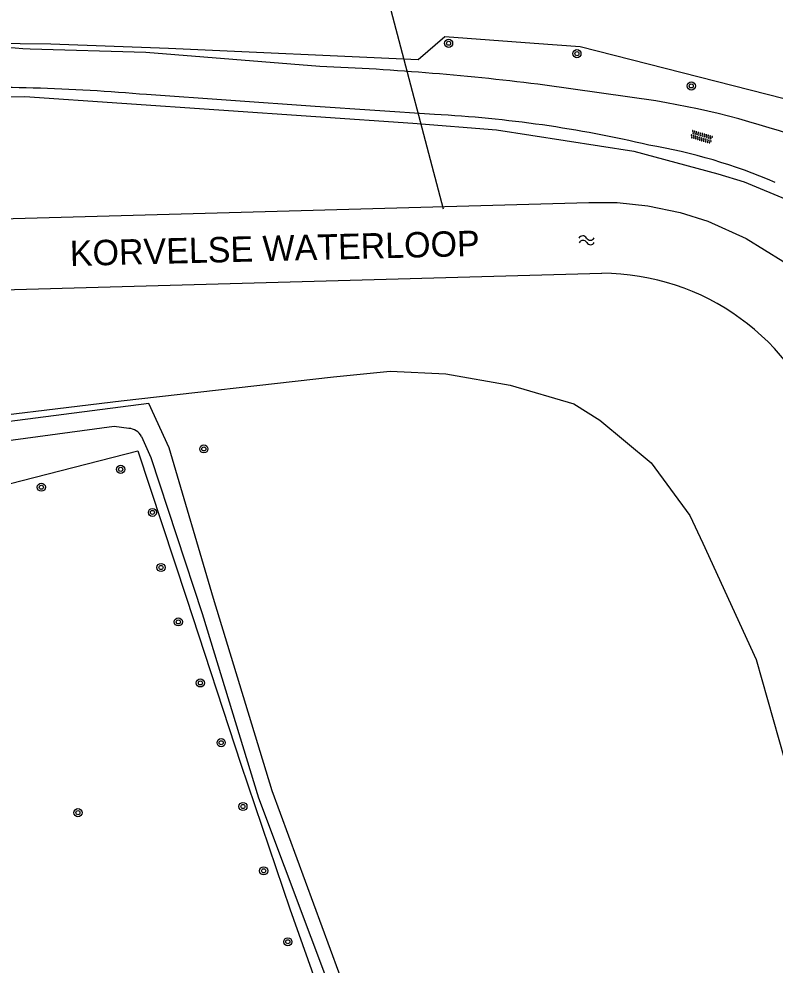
# Model space of a CAD drawing. Extents: x 135999 to 138000, y 396000 to 398501.
# Drawn here: x 136593.9 to 136668.2, y 396615.1 to 396708.2 of the extents above; entities that cross this region are included whole.
import ezdxf

# ---------------------------------------------------------------- set-up
doc = ezdxf.new("R2010")
doc.units = 0
for name, color, linetype in [('gg-afsc-faunaraster', 7, 'Continuous'), ('gg-afsc-lijn faunaraster', 7, 'Continuous'), ('gg-anno-naam water', 7, 'Continuous'), ('gg-knt-onverhard', 7, 'Continuous'), ('gg-kntw-beschoeiing', 7, 'Continuous'), ('gg-kwrk-duiker nz buis', 7, 'Continuous'), ('gt-symb-boom', 7, 'Continuous'), ('gt-symb-overige verharding', 7, 'Continuous'), ('gt-symb-watersymbool', 7, 'Continuous')]:
    doc.layers.add(name, color=color, linetype=linetype)

# ---------------------------------------------------------------- blocks, each defined once
blk = doc.blocks.new('gt0-OVH')
at = {"layer": 'gt-symb-overige verharding'}
for points in [[(-0.972, 0.298), (-0.967, 0.308), (-0.965, 0.319), (-0.966, 0.33), (-0.971, 0.34), (-0.978, 0.348), (-0.988, 0.353), (-0.999, 0.355), (-1.01, 0.354), (-1.02, 0.349), (-1.028, 0.342), (-1.033, 0.332), (-1.035, 0.321), (-1.034, 0.31), (-1.029, 0.3), (-1.022, 0.292), (-1.012, 0.287), (-1.001, 0.285), (-0.99, 0.286), (-0.98, 0.291)], [(-0.872, 0.106), (-0.867, 0.116), (-0.865, 0.126), (-0.866, 0.137), (-0.871, 0.147), (-0.878, 0.156), (-0.888, 0.161), (-0.899, 0.163), (-0.91, 0.162), (-0.92, 0.157), (-0.928, 0.15), (-0.933, 0.14), (-0.935, 0.129), (-0.934, 0.118), (-0.929, 0.108), (-0.922, 0.1), (-0.912, 0.095), (-0.901, 0.092), (-0.89, 0.094), (-0.88, 0.098)], [(-0.772, 0.298), (-0.767, 0.308), (-0.765, 0.319), (-0.766, 0.33), (-0.771, 0.34), (-0.778, 0.348), (-0.788, 0.353), (-0.799, 0.355), (-0.81, 0.354), (-0.82, 0.349), (-0.828, 0.342), (-0.833, 0.332), (-0.835, 0.321), (-0.834, 0.31), (-0.829, 0.3), (-0.822, 0.292), (-0.812, 0.287), (-0.801, 0.285), (-0.79, 0.286), (-0.78, 0.291)], [(-0.672, 0.106), (-0.667, 0.116), (-0.665, 0.126), (-0.666, 0.137), (-0.671, 0.147), (-0.678, 0.156), (-0.688, 0.161), (-0.699, 0.163), (-0.71, 0.162), (-0.72, 0.157), (-0.728, 0.15), (-0.733, 0.14), (-0.735, 0.129), (-0.734, 0.118), (-0.729, 0.108), (-0.722, 0.1), (-0.712, 0.095), (-0.701, 0.092), (-0.69, 0.094), (-0.68, 0.098)], [(-0.572, 0.298), (-0.567, 0.308), (-0.565, 0.319), (-0.566, 0.33), (-0.571, 0.34), (-0.578, 0.348), (-0.588, 0.353), (-0.599, 0.355), (-0.61, 0.354), (-0.62, 0.349), (-0.628, 0.342), (-0.633, 0.332), (-0.635, 0.321), (-0.634, 0.31), (-0.629, 0.3), (-0.622, 0.292), (-0.612, 0.287), (-0.601, 0.285), (-0.59, 0.286), (-0.58, 0.291)], [(-0.472, 0.106), (-0.467, 0.116), (-0.465, 0.126), (-0.466, 0.137), (-0.471, 0.147), (-0.478, 0.156), (-0.488, 0.161), (-0.499, 0.163), (-0.51, 0.162), (-0.52, 0.157), (-0.528, 0.15), (-0.533, 0.14), (-0.535, 0.129), (-0.534, 0.118), (-0.529, 0.108), (-0.522, 0.1), (-0.512, 0.095), (-0.501, 0.092), (-0.49, 0.094), (-0.48, 0.098)], [(-0.372, 0.298), (-0.367, 0.308), (-0.365, 0.319), (-0.366, 0.33), (-0.371, 0.34), (-0.378, 0.348), (-0.388, 0.353), (-0.399, 0.355), (-0.41, 0.354), (-0.42, 0.349), (-0.428, 0.342), (-0.433, 0.332), (-0.435, 0.321), (-0.434, 0.31), (-0.429, 0.3), (-0.422, 0.292), (-0.412, 0.287), (-0.401, 0.285), (-0.39, 0.286), (-0.38, 0.291)], [(-0.272, 0.106), (-0.267, 0.116), (-0.265, 0.126), (-0.266, 0.137), (-0.271, 0.147), (-0.278, 0.156), (-0.288, 0.161), (-0.299, 0.163), (-0.31, 0.162), (-0.32, 0.157), (-0.328, 0.15), (-0.333, 0.14), (-0.335, 0.129), (-0.334, 0.118), (-0.329, 0.108), (-0.322, 0.1), (-0.312, 0.095), (-0.301, 0.092), (-0.29, 0.094), (-0.28, 0.098)], [(-0.172, 0.298), (-0.167, 0.308), (-0.165, 0.319), (-0.166, 0.33), (-0.171, 0.34), (-0.178, 0.348), (-0.188, 0.353), (-0.199, 0.355), (-0.21, 0.354), (-0.22, 0.349), (-0.228, 0.342), (-0.233, 0.332), (-0.235, 0.321), (-0.234, 0.31), (-0.229, 0.3), (-0.222, 0.292), (-0.212, 0.287), (-0.201, 0.285), (-0.19, 0.286), (-0.18, 0.291)], [(-0.072, 0.106), (-0.067, 0.116), (-0.065, 0.126), (-0.066, 0.137), (-0.071, 0.147), (-0.078, 0.156), (-0.088, 0.161), (-0.099, 0.163), (-0.11, 0.162), (-0.12, 0.157), (-0.128, 0.15), (-0.133, 0.14), (-0.135, 0.129), (-0.134, 0.118), (-0.129, 0.108), (-0.122, 0.1), (-0.112, 0.095), (-0.101, 0.092), (-0.09, 0.094), (-0.08, 0.098)], [(0.028, 0.298), (0.033, 0.308), (0.035, 0.319), (0.034, 0.33), (0.029, 0.34), (0.022, 0.348), (0.012, 0.353), (0.001, 0.355), (-0.01, 0.354), (-0.02, 0.349), (-0.028, 0.342), (-0.033, 0.332), (-0.035, 0.321), (-0.034, 0.31), (-0.029, 0.3), (-0.022, 0.292), (-0.012, 0.287), (-0.001, 0.285), (0.01, 0.286), (0.02, 0.291)], [(0.128, 0.106), (0.133, 0.116), (0.135, 0.126), (0.134, 0.137), (0.129, 0.147), (0.122, 0.156), (0.112, 0.161), (0.101, 0.163), (0.09, 0.162), (0.08, 0.157), (0.072, 0.15), (0.067, 0.14), (0.065, 0.129), (0.066, 0.118), (0.071, 0.108), (0.078, 0.1), (0.088, 0.095), (0.099, 0.092), (0.11, 0.094), (0.12, 0.098)], [(0.228, 0.298), (0.233, 0.308), (0.235, 0.319), (0.234, 0.33), (0.229, 0.34), (0.222, 0.348), (0.212, 0.353), (0.201, 0.355), (0.19, 0.354), (0.18, 0.349), (0.172, 0.342), (0.167, 0.332), (0.165, 0.321), (0.166, 0.31), (0.171, 0.3), (0.178, 0.292), (0.188, 0.287), (0.199, 0.285), (0.21, 0.286), (0.22, 0.291)], [(0.328, 0.106), (0.333, 0.116), (0.335, 0.126), (0.334, 0.137), (0.329, 0.147), (0.322, 0.156), (0.312, 0.161), (0.301, 0.163), (0.29, 0.162), (0.28, 0.157), (0.272, 0.15), (0.267, 0.14), (0.265, 0.129), (0.266, 0.118), (0.271, 0.108), (0.278, 0.1), (0.288, 0.095), (0.299, 0.092), (0.31, 0.094), (0.32, 0.098)], [(0.428, 0.298), (0.433, 0.308), (0.435, 0.319), (0.434, 0.33), (0.429, 0.34), (0.422, 0.348), (0.412, 0.353), (0.401, 0.355), (0.39, 0.354), (0.38, 0.349), (0.372, 0.342), (0.367, 0.332), (0.365, 0.321), (0.366, 0.31), (0.371, 0.3), (0.378, 0.292), (0.388, 0.287), (0.399, 0.285), (0.41, 0.286), (0.42, 0.291)], [(0.528, 0.106), (0.533, 0.116), (0.535, 0.126), (0.534, 0.137), (0.529, 0.147), (0.522, 0.156), (0.512, 0.161), (0.501, 0.163), (0.49, 0.162), (0.48, 0.157), (0.472, 0.15), (0.467, 0.14), (0.465, 0.129), (0.466, 0.118), (0.471, 0.108), (0.478, 0.1), (0.488, 0.095), (0.499, 0.092), (0.51, 0.094), (0.52, 0.098)], [(0.628, 0.298), (0.633, 0.308), (0.635, 0.319), (0.634, 0.33), (0.629, 0.34), (0.622, 0.348), (0.612, 0.353), (0.601, 0.355), (0.59, 0.354), (0.58, 0.349), (0.572, 0.342), (0.567, 0.332), (0.565, 0.321), (0.566, 0.31), (0.571, 0.3), (0.578, 0.292), (0.588, 0.287), (0.599, 0.285), (0.61, 0.286), (0.62, 0.291)], [(0.728, 0.106), (0.733, 0.116), (0.735, 0.126), (0.734, 0.137), (0.729, 0.147), (0.722, 0.156), (0.712, 0.161), (0.701, 0.163), (0.69, 0.162), (0.68, 0.157), (0.672, 0.15), (0.667, 0.14), (0.665, 0.129), (0.666, 0.118), (0.671, 0.108), (0.678, 0.1), (0.688, 0.095), (0.699, 0.092), (0.71, 0.094), (0.72, 0.098)], [(0.828, 0.298), (0.833, 0.308), (0.835, 0.319), (0.834, 0.33), (0.829, 0.34), (0.822, 0.348), (0.812, 0.353), (0.801, 0.355), (0.79, 0.354), (0.78, 0.349), (0.772, 0.342), (0.767, 0.332), (0.765, 0.321), (0.766, 0.31), (0.771, 0.3), (0.778, 0.292), (0.788, 0.287), (0.799, 0.285), (0.81, 0.286), (0.82, 0.291)], [(0.928, 0.106), (0.933, 0.116), (0.935, 0.126), (0.934, 0.137), (0.929, 0.147), (0.922, 0.156), (0.912, 0.161), (0.901, 0.163), (0.89, 0.162), (0.88, 0.157), (0.872, 0.15), (0.867, 0.14), (0.865, 0.129), (0.866, 0.118), (0.871, 0.108), (0.878, 0.1), (0.888, 0.095), (0.899, 0.092), (0.91, 0.094), (0.92, 0.098)], [(1.028, 0.298), (1.033, 0.308), (1.035, 0.319), (1.034, 0.33), (1.029, 0.34), (1.022, 0.348), (1.012, 0.353), (1.001, 0.355), (0.99, 0.354), (0.98, 0.349), (0.972, 0.342), (0.967, 0.332), (0.965, 0.321), (0.966, 0.31), (0.971, 0.3), (0.978, 0.292), (0.988, 0.287), (0.999, 0.285), (1.01, 0.286), (1.02, 0.291)], [(-0.972, -0.142), (-0.967, -0.132), (-0.965, -0.121), (-0.966, -0.11), (-0.971, -0.1), (-0.978, -0.092), (-0.988, -0.087), (-0.999, -0.085), (-1.01, -0.086), (-1.02, -0.091), (-1.028, -0.098), (-1.033, -0.108), (-1.035, -0.119), (-1.034, -0.13), (-1.029, -0.14), (-1.022, -0.148), (-1.012, -0.153), (-1.001, -0.155), (-0.99, -0.154), (-0.98, -0.149)], [(-0.872, -0.334), (-0.867, -0.324), (-0.865, -0.314), (-0.866, -0.303), (-0.871, -0.293), (-0.878, -0.284), (-0.888, -0.279), (-0.899, -0.277), (-0.91, -0.278), (-0.92, -0.283), (-0.928, -0.29), (-0.933, -0.3), (-0.935, -0.311), (-0.934, -0.322), (-0.929, -0.332), (-0.922, -0.34), (-0.912, -0.345), (-0.901, -0.348), (-0.89, -0.346), (-0.88, -0.342)], [(-0.772, -0.142), (-0.767, -0.132), (-0.765, -0.121), (-0.766, -0.11), (-0.771, -0.1), (-0.778, -0.092), (-0.788, -0.087), (-0.799, -0.085), (-0.81, -0.086), (-0.82, -0.091), (-0.828, -0.098), (-0.833, -0.108), (-0.835, -0.119), (-0.834, -0.13), (-0.829, -0.14), (-0.822, -0.148), (-0.812, -0.153), (-0.801, -0.155), (-0.79, -0.154), (-0.78, -0.149)], [(-0.672, -0.334), (-0.667, -0.324), (-0.665, -0.314), (-0.666, -0.303), (-0.671, -0.293), (-0.678, -0.284), (-0.688, -0.279), (-0.699, -0.277), (-0.71, -0.278), (-0.72, -0.283), (-0.728, -0.29), (-0.733, -0.3), (-0.735, -0.311), (-0.734, -0.322), (-0.729, -0.332), (-0.722, -0.34), (-0.712, -0.345), (-0.701, -0.348), (-0.69, -0.346), (-0.68, -0.342)], [(-0.572, -0.142), (-0.567, -0.132), (-0.565, -0.121), (-0.566, -0.11), (-0.571, -0.1), (-0.578, -0.092), (-0.588, -0.087), (-0.599, -0.085), (-0.61, -0.086), (-0.62, -0.091), (-0.628, -0.098), (-0.633, -0.108), (-0.635, -0.119), (-0.634, -0.13), (-0.629, -0.14), (-0.622, -0.148), (-0.612, -0.153), (-0.601, -0.155), (-0.59, -0.154), (-0.58, -0.149)], [(-0.472, -0.334), (-0.467, -0.324), (-0.465, -0.314), (-0.466, -0.303), (-0.471, -0.293), (-0.478, -0.284), (-0.488, -0.279), (-0.499, -0.277), (-0.51, -0.278), (-0.52, -0.283), (-0.528, -0.29), (-0.533, -0.3), (-0.535, -0.311), (-0.534, -0.322), (-0.529, -0.332), (-0.522, -0.34), (-0.512, -0.345), (-0.501, -0.348), (-0.49, -0.346), (-0.48, -0.342)], [(-0.372, -0.142), (-0.367, -0.132), (-0.365, -0.121), (-0.366, -0.11), (-0.371, -0.1), (-0.378, -0.092), (-0.388, -0.087), (-0.399, -0.085), (-0.41, -0.086), (-0.42, -0.091), (-0.428, -0.098), (-0.433, -0.108), (-0.435, -0.119), (-0.434, -0.13), (-0.429, -0.14), (-0.422, -0.148), (-0.412, -0.153), (-0.401, -0.155), (-0.39, -0.154), (-0.38, -0.149)], [(-0.272, -0.334), (-0.267, -0.324), (-0.265, -0.314), (-0.266, -0.303), (-0.271, -0.293), (-0.278, -0.284), (-0.288, -0.279), (-0.299, -0.277), (-0.31, -0.278), (-0.32, -0.283), (-0.328, -0.29), (-0.333, -0.3), (-0.335, -0.311), (-0.334, -0.322), (-0.329, -0.332), (-0.322, -0.34), (-0.312, -0.345), (-0.301, -0.348), (-0.29, -0.346), (-0.28, -0.342)], [(-0.172, -0.142), (-0.167, -0.132), (-0.165, -0.121), (-0.166, -0.11), (-0.171, -0.1), (-0.178, -0.092), (-0.188, -0.087), (-0.199, -0.085), (-0.21, -0.086), (-0.22, -0.091), (-0.228, -0.098), (-0.233, -0.108), (-0.235, -0.119), (-0.234, -0.13), (-0.229, -0.14), (-0.222, -0.148), (-0.212, -0.153), (-0.201, -0.155), (-0.19, -0.154), (-0.18, -0.149)], [(-0.072, -0.334), (-0.067, -0.324), (-0.065, -0.314), (-0.066, -0.303), (-0.071, -0.293), (-0.078, -0.284), (-0.088, -0.279), (-0.099, -0.277), (-0.11, -0.278), (-0.12, -0.283), (-0.128, -0.29), (-0.133, -0.3), (-0.135, -0.311), (-0.134, -0.322), (-0.129, -0.332), (-0.122, -0.34), (-0.112, -0.345), (-0.101, -0.348), (-0.09, -0.346), (-0.08, -0.342)], [(0.028, -0.142), (0.033, -0.132), (0.035, -0.121), (0.034, -0.11), (0.029, -0.1), (0.022, -0.092), (0.012, -0.087), (0.001, -0.085), (-0.01, -0.086), (-0.02, -0.091), (-0.028, -0.098), (-0.033, -0.108), (-0.035, -0.119), (-0.034, -0.13), (-0.029, -0.14), (-0.022, -0.148), (-0.012, -0.153), (-0.001, -0.155), (0.01, -0.154), (0.02, -0.149)], [(0.128, -0.334), (0.133, -0.324), (0.135, -0.314), (0.134, -0.303), (0.129, -0.293), (0.122, -0.284), (0.112, -0.279), (0.101, -0.277), (0.09, -0.278), (0.08, -0.283), (0.072, -0.29), (0.067, -0.3), (0.065, -0.311), (0.066, -0.322), (0.071, -0.332), (0.078, -0.34), (0.088, -0.345), (0.099, -0.348), (0.11, -0.346), (0.12, -0.342)], [(0.228, -0.142), (0.233, -0.132), (0.235, -0.121), (0.234, -0.11), (0.229, -0.1), (0.222, -0.092), (0.212, -0.087), (0.201, -0.085), (0.19, -0.086), (0.18, -0.091), (0.172, -0.098), (0.167, -0.108), (0.165, -0.119), (0.166, -0.13), (0.171, -0.14), (0.178, -0.148), (0.188, -0.153), (0.199, -0.155), (0.21, -0.154), (0.22, -0.149)], [(0.328, -0.334), (0.333, -0.324), (0.335, -0.314), (0.334, -0.303), (0.329, -0.293), (0.322, -0.284), (0.312, -0.279), (0.301, -0.277), (0.29, -0.278), (0.28, -0.283), (0.272, -0.29), (0.267, -0.3), (0.265, -0.311), (0.266, -0.322), (0.271, -0.332), (0.278, -0.34), (0.288, -0.345), (0.299, -0.348), (0.31, -0.346), (0.32, -0.342)], [(0.428, -0.142), (0.433, -0.132), (0.435, -0.121), (0.434, -0.11), (0.429, -0.1), (0.422, -0.092), (0.412, -0.087), (0.401, -0.085), (0.39, -0.086), (0.38, -0.091), (0.372, -0.098), (0.367, -0.108), (0.365, -0.119), (0.366, -0.13), (0.371, -0.14), (0.378, -0.148), (0.388, -0.153), (0.399, -0.155), (0.41, -0.154), (0.42, -0.149)], [(0.528, -0.334), (0.533, -0.324), (0.535, -0.314), (0.534, -0.303), (0.529, -0.293), (0.522, -0.284), (0.512, -0.279), (0.501, -0.277), (0.49, -0.278), (0.48, -0.283), (0.472, -0.29), (0.467, -0.3), (0.465, -0.311), (0.466, -0.322), (0.471, -0.332), (0.478, -0.34), (0.488, -0.345), (0.499, -0.348), (0.51, -0.346), (0.52, -0.342)], [(0.628, -0.142), (0.633, -0.132), (0.635, -0.121), (0.634, -0.11), (0.629, -0.1), (0.622, -0.092), (0.612, -0.087), (0.601, -0.085), (0.59, -0.086), (0.58, -0.091), (0.572, -0.098), (0.567, -0.108), (0.565, -0.119), (0.566, -0.13), (0.571, -0.14), (0.578, -0.148), (0.588, -0.153), (0.599, -0.155), (0.61, -0.154), (0.62, -0.149)], [(0.728, -0.334), (0.733, -0.324), (0.735, -0.314), (0.734, -0.303), (0.729, -0.293), (0.722, -0.284), (0.712, -0.279), (0.701, -0.277), (0.69, -0.278), (0.68, -0.283), (0.672, -0.29), (0.667, -0.3), (0.665, -0.311), (0.666, -0.322), (0.671, -0.332), (0.678, -0.34), (0.688, -0.345), (0.699, -0.348), (0.71, -0.346), (0.72, -0.342)], [(0.828, -0.142), (0.833, -0.132), (0.835, -0.121), (0.834, -0.11), (0.829, -0.1), (0.822, -0.092), (0.812, -0.087), (0.801, -0.085), (0.79, -0.086), (0.78, -0.091), (0.772, -0.098), (0.767, -0.108), (0.765, -0.119), (0.766, -0.13), (0.771, -0.14), (0.778, -0.148), (0.788, -0.153), (0.799, -0.155), (0.81, -0.154), (0.82, -0.149)], [(0.928, -0.334), (0.933, -0.324), (0.935, -0.314), (0.934, -0.303), (0.929, -0.293), (0.922, -0.284), (0.912, -0.279), (0.901, -0.277), (0.89, -0.278), (0.88, -0.283), (0.872, -0.29), (0.867, -0.3), (0.865, -0.311), (0.866, -0.322), (0.871, -0.332), (0.878, -0.34), (0.888, -0.345), (0.899, -0.348), (0.91, -0.346), (0.92, -0.342)], [(1.028, -0.142), (1.033, -0.132), (1.035, -0.121), (1.034, -0.11), (1.029, -0.1), (1.022, -0.092), (1.012, -0.087), (1.001, -0.085), (0.99, -0.086), (0.98, -0.091), (0.972, -0.098), (0.967, -0.108), (0.965, -0.119), (0.966, -0.13), (0.971, -0.14), (0.978, -0.148), (0.988, -0.153), (0.999, -0.155), (1.01, -0.154), (1.02, -0.149)]]:
    blk.add_lwpolyline(points, close=True, dxfattribs=at)
blk = doc.blocks.new('gt0-BOOM')
at = {"layer": 'gt-symb-boom'}
for radius in [0.4, 0.2]:
    blk.add_circle((0, 0), radius, dxfattribs=at)
blk = doc.blocks.new('gt0-WA')
at = {"layer": 'gt-symb-watersymbool'}
for centre, start, end in [((-0.323, 0.022), 28.07249, 151.92751), ((0.427, 0.422), 208.07248, 331.92751), ((-0.323, -0.428), 28.07249, 151.92751), ((0.427, -0.028), 208.07248, 331.92751)]:
    blk.add_arc(centre, 0.425, start, end, dxfattribs=at)

msp = doc.modelspace()

# ---------------------------------------------------------------- linework, layer by layer
at = {"layer": 'gg-afsc-faunaraster'}
for points in [[(136517.624, 396692.073), (136528.75, 396695.069), (136551.833, 396700.288), (136572.338, 396704.791), (136581.264, 396705.909), (136587.913, 396705.873), (136597.004, 396705.787), (136608.593, 396705.356), (136633.149, 396704.234), (136635.782, 396706.496), (136644.569, 396705.843)], [(136644.569, 396705.843), (136649.083, 396705.507), (136689.198, 396695.296)], [(136588.597, 396700.568), (136594.457, 396700.591), (136632.617, 396697.965), (136640.85, 396697.324), (136654.351, 396695.206), (136662.618, 396692.986), (136665.22, 396692.199), (136673.785, 396688.625), (136678.766, 396685.309), (136683.09, 396681.141), (136686.274, 396676.271), (136689.544, 396670.436), (136693.249, 396662.438), (136695.972, 396653.884), (136701.539, 396628.214), (136702.258, 396625.295), (136703.538, 396622.538), (136705.797, 396620.644), (136708.721, 396619.55), (136711.585, 396619.939), (136715.458, 396621.217)], [(136550.316, 396664.161), (136603.929, 396670.667), (136624.808, 396673.004), (136630.395, 396673.561), (136635.871, 396673.305), (136642.208, 396672.19), (136648.47, 396670.351), (136651.008, 396668.743), (136656.059, 396664.564), (136659.85, 396659.38), (136661.144, 396656.652), (136666.388, 396645.214), (136669.73, 396633.384), (136680.865, 396594.068), (136683.489, 396588.708), (136687.52, 396583.447), (136689.634, 396581.626), (136692.164, 396580.039), (136704.126, 396574.477), (136731.649, 396571.967)], [(136521.616, 396620.485), (136513.26, 396642.053), (136605.568, 396665.739), (136610.374, 396651.252), (136615.689, 396634.905), (136620.53, 396620.664), (136625.684, 396606.181), (136631.209, 396592.464), (136633.323, 396587.331), (136634.192, 396584.968)]]:
    msp.add_lwpolyline(points, dxfattribs=at)
at = {"layer": 'gg-afsc-lijn faunaraster'}
for points in [[(136517.624, 396692.073), (136528.75, 396695.069), (136551.833, 396700.288), (136572.338, 396704.791), (136581.264, 396705.909), (136587.913, 396705.873), (136597.004, 396705.787), (136608.593, 396705.356), (136633.149, 396704.234), (136635.782, 396706.496), (136644.569, 396705.843)], [(136644.569, 396705.843), (136649.083, 396705.507), (136689.198, 396695.296)]]:
    msp.add_lwpolyline(points, dxfattribs=at)
at = {"layer": 'gg-knt-onverhard'}
msp.add_line((136656.523, 396700.155), (136645.597, 396701.707), dxfattribs=at)
for points in [[(136623.474, 396703.55), (136606.345, 396704.94), (136594.998, 396705.247)], [(136634.756, 396698.822), (136623.021, 396699.605), (136606.442, 396700.777)], [(136632.015, 396597.549), (136630.382, 396601.92), (136626.167, 396612.223), (136618.793, 396632.286), (136613.022, 396651.202), (136608.644, 396666.041), (136606.644, 396670.382), (136579.781, 396666.929), (136553.363, 396663.829)], [(136604.679, 396667.942), (136603.248, 396668.124), (136579.489, 396664.915), (136553.73, 396661.772)], [(136605.934, 396667.148), (136606.862, 396665.087), (136611.895, 396649.717), (136617.437, 396631.589), (136625.097, 396611.153), (136628.972, 396601.266), (136633.114, 396590.866), (136635.198, 396584.585)]]:
    msp.add_lwpolyline(points, dxfattribs=at)
for centre, radius, start, end in [((136588.384, 396605.461), 100.005, 86.20784, 99.76518), ((136613.538, 396450.579), 253.166, 82.72497, 87.75075), ((136590.154, 396517.6), 183.9, 84.91851, 91.87797), ((136642.789, 396617.072), 84.211, 69.25732, 80.61362), ((136628.598, 396580.226), 118.756, 76.74494, 87.0276), ((136646.718, 396642.308), 54.28, 66.63308, 80.33872), ((136604.547, 396666.344), 1.604, 30.09653, 85.2629)]:
    msp.add_arc(centre, radius, start, end, dxfattribs=at)
at = {"layer": 'gg-kntw-beschoeiing'}
for points in [[(136530.838, 396682.665), (136537.5, 396685.78), (136539.16, 396686.428), (136540.883, 396686.884), (136542.309, 396687.108), (136543.748, 396687.2), (136649.93, 396690.16), (136652.72, 396690.151), (136655.72, 396689.85), (136658.898, 396689.194), (136661.625, 396688.334), (136665.409, 396686.636), (136669, 396684.379), (136671.911, 396681.976), (136674.03, 396679.776)], [(136475.411, 396649.074), (136540.63, 396679.53), (136542.22, 396680.041), (136543.89, 396680.231), (136651.21, 396683.2)]]:
    msp.add_lwpolyline(points, dxfattribs=at)
msp.add_arc((136651.162, 396659.931), 23.269, 18.19308, 89.88201, dxfattribs=at)
at = {"layer": 'gg-kwrk-duiker nz buis'}
msp.add_line((136629.942, 396711.021), (136635.597, 396689.557), dxfattribs=at)

# ---------------------------------------------------------------- block references
at = {"layer": 'gt-symb-boom'}
for p in [(136636.137, 396705.831), (136648.758, 396704.809), (136660.005, 396701.633), (136612.063, 396665.922), (136603.888, 396663.912), (136596.084, 396662.153), (136607.012, 396659.674), (136607.854, 396654.255), (136609.558, 396648.903), (136611.727, 396642.899), (136613.77, 396637.015), (136615.91, 396630.744), (136599.685, 396630.132), (136617.953, 396624.409), (136620.326, 396617.434)]:
    msp.add_blockref('gt0-BOOM', p, dxfattribs=at)
at = {"layer": 'gt-symb-overige verharding', "rotation": -16.441280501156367}
msp.add_blockref('gt0-OVH', (136661.013, 396696.611), dxfattribs=at)
at = {"layer": 'gt-symb-watersymbool', "rotation": 1.603862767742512}
msp.add_blockref('gt0-WA', (136649.662, 396686.448), dxfattribs=at)

# ---------------------------------------------------------------- texts
at = {"layer": 'gg-anno-naam water'}
msp.add_text('KORVELSE WATERLOOP', height=2.5, rotation=1.4321, dxfattribs=at).set_placement((136598.92, 396683.909))

doc.saveas('drawing.dxf')
